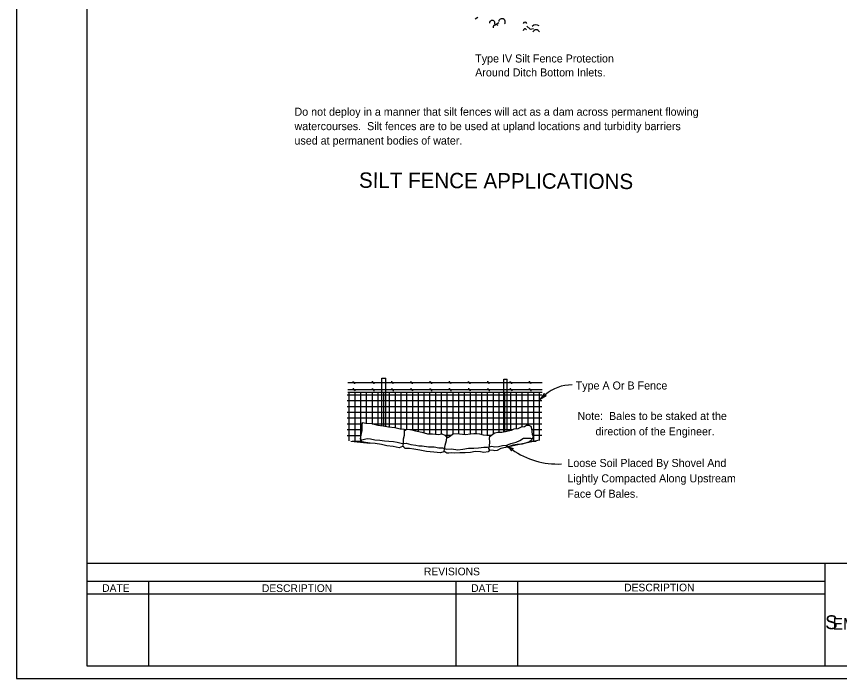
# Model space of a CAD drawing. Extents: x 539344 to 540004, y 1574686 to 1575110.
# Drawn here: x 539344 to 539600.9, y 1574686.5 to 1574893 of the extents above; entities that cross this region are included whole.
import ezdxf

# ---------------------------------------------------------------- set-up
doc = ezdxf.new("R2010")
doc.units = 0
for name, color, linetype in [('AdhocPoint_dp', 7, 'Continuous'), ('Default', 7, 'Continuous'), ('Logo_dp', 7, 'Continuous'), ('PlotBorder_dp', 7, 'Continuous'), ('ScratchEle_dp', 7, 'Continuous'), ('SheetBorder_dp', 7, 'Continuous'), ('SheetLines_dp', 7, 'Continuous'), ('TextMisc', 7, 'Continuous')]:
    doc.layers.add(name, color=color, linetype=linetype)

msp = doc.modelspace()

# ---------------------------------------------------------------- linework, layer by layer
at = {"layer": 'AdhocPoint_dp'}
msp.add_line((539343.95, 1574686.45), (539343.95, 1574686.45), dxfattribs=at)
at = {"layer": 'Default'}
for p, q in [((539487.11, 1574892.32), (539488.04, 1574892.79)), ((539493.16, 1574890.34), (539494.56, 1574891.16)), ((539503.28, 1574889.99), (539504.33, 1574889.06)), ((539504.33, 1574889.06), (539505.38, 1574889.29)), ((539458.05, 1574765.36), (539458.05, 1574780.14)), ((539458.05, 1574780.14), (539459.27, 1574780.14)), ((539459.27, 1574765.12), (539459.27, 1574780.14)), ((539496.14, 1574763.43), (539496.14, 1574779.9)), ((539496.14, 1574779.9), (539497.18, 1574779.9)), ((539497.18, 1574763.68), (539497.18, 1574779.9)), ((539447.41, 1574778.78), (539508.05, 1574778.78)), ((539447.45, 1574776.59), (539508.05, 1574776.59)), ((539447.2, 1574774.96), (539507.98, 1574774.96)), ((539447.45, 1574775.8), (539508.05, 1574775.8)), ((539447.76, 1574775.8), (539447.76, 1574760.62)), ((539449.56, 1574775.8), (539449.56, 1574760.41)), ((539451.36, 1574775.8), (539451.36, 1574760.21)), ((539453.16, 1574775.8), (539453.16, 1574766.09)), ((539454.96, 1574775.8), (539454.96, 1574765.96)), ((539456.76, 1574775.8), (539456.76, 1574765.53)), ((539458.56, 1574775.8), (539458.56, 1574765.28)), ((539460.35, 1574775.82), (539460.35, 1574764.91)), ((539462.15, 1574775.82), (539462.15, 1574764.73)), ((539463.95, 1574775.82), (539463.95, 1574764.38)), ((539465.75, 1574775.82), (539465.75, 1574764.29)), ((539467.55, 1574775.82), (539467.55, 1574763.96)), ((539469.35, 1574775.82), (539469.35, 1574763.56)), ((539471.15, 1574775.82), (539471.15, 1574763.16)), ((539472.95, 1574775.82), (539472.95, 1574762.84)), ((539474.75, 1574775.82), (539474.75, 1574762.74)), ((539476.55, 1574775.84), (539476.55, 1574762.8)), ((539478.35, 1574775.84), (539478.35, 1574761.54)), ((539480.15, 1574775.84), (539480.15, 1574762.67)), ((539481.95, 1574775.84), (539481.95, 1574762.8)), ((539483.75, 1574775.84), (539483.75, 1574762.61)), ((539485.55, 1574775.84), (539485.55, 1574762.74)), ((539487.35, 1574775.84), (539487.35, 1574762.88)), ((539489.15, 1574775.84), (539489.15, 1574762.61)), ((539490.95, 1574775.84), (539490.95, 1574762.36)), ((539492.75, 1574775.86), (539492.75, 1574762.81)), ((539494.55, 1574775.86), (539494.55, 1574763.28)), ((539496.35, 1574775.86), (539496.35, 1574763.45)), ((539498.15, 1574775.86), (539498.15, 1574763.9)), ((539499.95, 1574775.86), (539499.95, 1574764.42)), ((539501.75, 1574775.86), (539501.75, 1574765.01)), ((539503.55, 1574775.86), (539503.55, 1574765.53)), ((539505.35, 1574775.86), (539505.35, 1574760.38)), ((539507.15, 1574775.86), (539507.15, 1574760.77)), ((539509.01, 1574774.95), (539508.81, 1574775.34)), ((539509.36, 1574774.64), (539509.01, 1574774.95)), ((539447.2, 1574773.15), (539507.98, 1574773.16)), ((539447.2, 1574771.36), (539507.98, 1574771.36)), ((539447.2, 1574769.56), (539507.98, 1574769.56)), ((539447.2, 1574767.76), (539507.98, 1574767.76)), ((539447.2, 1574765.9), (539451.93, 1574765.9)), ((539447.2, 1574764.1), (539451.87, 1574764.1)), ((539454.98, 1574765.96), (539507.98, 1574765.96)), ((539464.99, 1574764.12), (539465.51, 1574764.12)), ((539466.8, 1574764.16), (539498.96, 1574764.16)), ((539504.8, 1574764.16), (539507.98, 1574764.16)), ((539447.2, 1574762.3), (539451.56, 1574762.3)), ((539477.72, 1574762.34), (539479.67, 1574762.34)), ((539491.7, 1574762.36), (539492.16, 1574762.36)), ((539505.09, 1574762.36), (539507.98, 1574762.36)), ((539448.31, 1574760.56), (539454.3, 1574759.87)), ((539448.8, 1574760.5), (539451.66, 1574760.5)), ((539507.26, 1574760.8), (539496.6, 1574758.49)), ((539504.4, 1574760.56), (539506.16, 1574760.56)), ((539504.45, 1574760.59), (539504.45, 1574760.19)), ((539498.55, 1574757.49), (539498.73, 1574757.92)), ((539498.73, 1574757.92), (539499.04, 1574758.24))]:
    msp.add_line(p, q, dxfattribs=at)
for points in [[(539507.21, 1574773.51), (539508.09, 1574774.37), (539508.42, 1574774.79), (539508.81, 1574775.34)], [(539507.21, 1574773.51), (539508.26, 1574774.16), (539508.74, 1574774.39), (539509.36, 1574774.64)], [(539507.98, 1574774.11), (539508.25, 1574774.29), (539508.43, 1574774.39), (539508.58, 1574774.48), (539508.71, 1574774.54), (539508.9, 1574774.62), (539508.76, 1574774.73), (539508.67, 1574774.9), (539508.59, 1574774.75), (539508.51, 1574774.65), (539508.42, 1574774.55), (539508.34, 1574774.45), (539508.25, 1574774.37), (539508.16, 1574774.27), (539507.98, 1574774.11)], [(539451.65, 1574760.52), (539451.35, 1574761.19), (539451.57, 1574762.35), (539451.88, 1574763.82), (539451.83, 1574765.25), (539451.99, 1574766.32), (539453.06, 1574766.1), (539454.86, 1574765.99), (539456.72, 1574765.54), (539458.42, 1574765.31), (539460.05, 1574764.94), (539462.13, 1574764.73), (539463.73, 1574764.4), (539464.99, 1574764.28), (539464.99, 1574762.25), (539464.7, 1574761.18), (539464.7, 1574759.66), (539464.47, 1574758.81), (539463.45, 1574758.46), (539461.61, 1574758.85), (539459.63, 1574759.04), (539457.96, 1574759.45), (539455.96, 1574759.76), (539454.34, 1574759.86), (539452.88, 1574760.05), (539451.9, 1574760.28), (539451.65, 1574760.52)], [(539464.99, 1574763.74), (539465.75, 1574764.29), (539467.01, 1574764.11), (539468.57, 1574763.7), (539470.5, 1574763.35), (539472.28, 1574762.82), (539473.8, 1574762.85), (539475.66, 1574762.62), (539476.76, 1574762.84), (539477.74, 1574762.35), (539478.23, 1574761.91), (539478.12, 1574760.58), (539477.74, 1574759.11), (539477.51, 1574758.1), (539477.34, 1574757.18), (539476.3, 1574756.83), (539474.26, 1574757.08), (539472, 1574757.3), (539469.93, 1574757.71), (539468.05, 1574757.97), (539466.63, 1574758.24), (539465.33, 1574758.19), (539464.87, 1574758.59), (539464.5, 1574758.92)], [(539491.64, 1574761.95), (539492.12, 1574762.33), (539492.73, 1574762.8), (539493.25, 1574763.1), (539494.19, 1574763.27), (539495.53, 1574763.3), (539496.58, 1574763.52), (539497.5, 1574763.77), (539498.54, 1574763.98), (539499.36, 1574764.33), (539500.59, 1574764.51), (539501.63, 1574765), (539502.61, 1574765.09), (539503.14, 1574765.55), (539503.94, 1574765.52), (539504.58, 1574765.2), (539504.79, 1574764.5), (539504.82, 1574763.39), (539504.99, 1574762.69), (539505.24, 1574761.85), (539504.77, 1574760.82), (539504.11, 1574760.35), (539503.18, 1574759.94), (539501.82, 1574759.62), (539500.32, 1574759.5), (539498.91, 1574759.31), (539497.79, 1574758.89), (539496.64, 1574758.5), (539495.22, 1574758.21), (539494.07, 1574757.64), (539493.33, 1574757.45), (539492.87, 1574757.65), (539491.67, 1574757.7)], [(539451.49, 1574760.89), (539452.15, 1574761.05), (539453.44, 1574761.3), (539454.53, 1574761.24), (539455.85, 1574760.95), (539457.35, 1574760.82), (539458.83, 1574760.59), (539460.21, 1574760.55), (539461.65, 1574760.36), (539462.85, 1574760.17), (539464.44, 1574759.83), (539465.57, 1574759.86), (539467.1, 1574759.47), (539468.62, 1574759.28), (539469.54, 1574759.04), (539470.62, 1574759.03), (539472.58, 1574758.78), (539474.34, 1574758.71), (539475.82, 1574758.47), (539476.94, 1574758.4), (539478.25, 1574758.01), (539479.79, 1574758.09), (539481.75, 1574757.85), (539483.29, 1574758.01), (539485.06, 1574758.29), (539486.76, 1574758.28), (539488.22, 1574758.45), (539489.86, 1574758.66), (539491, 1574758.68), (539492.31, 1574758.97), (539493.23, 1574758.72), (539494.45, 1574758.81), (539495.67, 1574759.11), (539497.01, 1574759.22), (539498.34, 1574759.79), (539499.94, 1574760.21), (539501.13, 1574760.74), (539502.24, 1574761.41), (539503.52, 1574761.47), (539504.5, 1574761.48), (539505.01, 1574761.34)], [(539478.19, 1574761.47), (539478.85, 1574761.75), (539479.56, 1574762.26), (539480.44, 1574762.87), (539482.26, 1574762.78), (539484.1, 1574762.57), (539485.74, 1574762.76), (539486.75, 1574762.9), (539487.63, 1574762.87), (539488.5, 1574762.81), (539489.64, 1574762.46), (539490.76, 1574762.38), (539491.7, 1574762.35), (539491.57, 1574761.48), (539491.6, 1574760.2), (539491.49, 1574759.05), (539491.34, 1574758.24), (539491.67, 1574757.7), (539491.17, 1574757.2), (539489.87, 1574756.99), (539488.81, 1574757.18), (539487.13, 1574757.25), (539485.66, 1574756.96), (539484, 1574756.89), (539482.41, 1574756.89), (539480.82, 1574756.74), (539479.86, 1574756.85), (539478.9, 1574756.72), (539478.3, 1574756.76), (539477.39, 1574757.42)], [(539496.79, 1574759.18), (539497.9, 1574758.62), (539498.4, 1574758.44), (539499.04, 1574758.24)], [(539496.79, 1574759.18), (539497.75, 1574758.39), (539498.12, 1574758), (539498.55, 1574757.49)], [(539497.61, 1574758.64), (539497.87, 1574758.44), (539498.02, 1574758.3), (539498.15, 1574758.18), (539498.24, 1574758.08), (539498.39, 1574757.93), (539498.45, 1574758.09), (539498.58, 1574758.23), (539498.41, 1574758.26), (539498.29, 1574758.3), (539498.17, 1574758.36), (539498.05, 1574758.4), (539497.94, 1574758.46), (539497.82, 1574758.52), (539497.61, 1574758.64)]]:
    msp.add_lwpolyline(points, dxfattribs=at)
for centre, radius, start, end in [((539495.51, 1574891.29), 1.03, 325.2278, 170.0212), ((539492.48, 1574890.97), 0.847, 341.695, 183.1066), ((539493.67, 1574889.55), 0.936, 40.2418, 183.3251), ((539502.74, 1574890.69), 0.564, 12.6804, 167.3196), ((539506.11, 1574888.61), 1.77, 54.4144, 131.3157), ((539502.69, 1574888.65), 0.522, 21.3706, 195.4993), ((539506.2, 1574887.74), 1.13, 22.894, 157.106), ((539449.38, 1574779.17), 0.388, 174.2815, 250.0227), ((539455.38, 1574779.17), 0.388, 174.2815, 250.0227), ((539461.38, 1574779.17), 0.388, 174.2815, 250.0227), ((539467.38, 1574779.17), 0.388, 174.2815, 250.0227), ((539473.38, 1574779.17), 0.388, 174.2815, 250.0227), ((539479.38, 1574779.17), 0.388, 174.2815, 250.0227), ((539485.38, 1574779.17), 0.388, 174.2815, 250.0227), ((539491.38, 1574779.17), 0.388, 174.2815, 250.0227), ((539498.38, 1574779.17), 0.388, 174.2815, 250.0227), ((539504.38, 1574779.17), 0.388, 174.2815, 250.0227), ((539449.42, 1574776.98), 0.388, 174.2815, 250.0227), ((539449.32, 1574778.79), 0.073, 0, 180), ((539449.32, 1574778.79), 0.073, 180, 0), ((539449.36, 1574776.59), 0.073, 0, 180), ((539449.36, 1574776.59), 0.073, 180, 0), ((539449.25, 1574778.4), 0.388, 354.2815, 69.465), ((539449.29, 1574776.2), 0.388, 354.2815, 69.465), ((539455.42, 1574776.98), 0.388, 174.2815, 250.0227), ((539455.32, 1574778.79), 0.073, 0, 180), ((539455.32, 1574778.79), 0.073, 180, 0), ((539455.36, 1574776.59), 0.073, 0, 180), ((539455.36, 1574776.59), 0.073, 180, 0), ((539455.25, 1574778.4), 0.388, 354.2815, 69.465), ((539455.29, 1574776.2), 0.388, 354.2815, 69.465), ((539461.42, 1574776.98), 0.388, 174.2815, 250.0227), ((539461.32, 1574778.79), 0.073, 0, 180), ((539461.32, 1574778.79), 0.073, 180, 0), ((539461.36, 1574776.59), 0.073, 0, 180), ((539461.36, 1574776.59), 0.073, 180, 0), ((539461.25, 1574778.4), 0.388, 354.2815, 69.465), ((539461.29, 1574776.2), 0.388, 354.2815, 69.465), ((539467.42, 1574776.98), 0.388, 174.2815, 250.0227), ((539467.32, 1574778.79), 0.073, 0, 180), ((539467.32, 1574778.79), 0.073, 180, 0), ((539467.36, 1574776.59), 0.073, 0, 180), ((539467.36, 1574776.59), 0.073, 180, 0), ((539467.25, 1574778.4), 0.388, 354.2815, 69.465), ((539467.29, 1574776.2), 0.388, 354.2815, 69.465), ((539473.42, 1574776.98), 0.388, 174.2815, 250.0227), ((539473.32, 1574778.79), 0.073, 0, 180), ((539473.32, 1574778.79), 0.073, 180, 0), ((539473.36, 1574776.59), 0.073, 0, 180), ((539473.36, 1574776.59), 0.073, 180, 0), ((539473.25, 1574778.4), 0.388, 354.2815, 69.465), ((539473.29, 1574776.2), 0.388, 354.2815, 69.465), ((539479.42, 1574776.98), 0.388, 174.2815, 250.0227), ((539479.32, 1574778.79), 0.073, 0, 180), ((539479.32, 1574778.79), 0.073, 180, 0), ((539479.36, 1574776.59), 0.073, 0, 180), ((539479.36, 1574776.59), 0.073, 180, 0), ((539479.25, 1574778.4), 0.388, 354.2815, 69.465), ((539479.29, 1574776.2), 0.388, 354.2815, 69.465), ((539485.42, 1574776.98), 0.388, 174.2815, 250.0227), ((539485.32, 1574778.79), 0.073, 0, 180), ((539485.32, 1574778.79), 0.073, 180, 0), ((539485.36, 1574776.59), 0.073, 0, 180), ((539485.36, 1574776.59), 0.073, 180, 0), ((539485.25, 1574778.4), 0.388, 354.2815, 69.465), ((539485.29, 1574776.2), 0.388, 354.2815, 69.465), ((539491.42, 1574776.98), 0.388, 174.2815, 250.0227), ((539491.32, 1574778.79), 0.073, 0, 180), ((539491.32, 1574778.79), 0.073, 180, 0), ((539491.36, 1574776.59), 0.073, 0, 180), ((539491.36, 1574776.59), 0.073, 180, 0), ((539491.25, 1574778.4), 0.388, 354.2815, 69.465), ((539491.29, 1574776.2), 0.388, 354.2815, 69.465), ((539498.42, 1574776.98), 0.388, 174.2815, 250.0227), ((539498.32, 1574778.79), 0.073, 0, 180), ((539498.32, 1574778.79), 0.073, 180, 0), ((539498.36, 1574776.59), 0.073, 0, 180), ((539498.36, 1574776.59), 0.073, 180, 0), ((539498.25, 1574778.4), 0.388, 354.2815, 69.465), ((539498.29, 1574776.2), 0.388, 354.2815, 69.465), ((539504.42, 1574776.98), 0.388, 174.2815, 250.0227), ((539504.32, 1574778.79), 0.073, 0, 180), ((539504.32, 1574778.79), 0.073, 180, 0), ((539504.36, 1574776.59), 0.073, 0, 180), ((539504.36, 1574776.59), 0.073, 180, 0), ((539504.25, 1574778.4), 0.388, 354.2815, 69.465), ((539504.29, 1574776.2), 0.388, 354.2815, 69.465), ((539517.37, 1574765.27), 12.79, 89.4818, 130.8193), ((539512.69, 1574777.12), 23.74, 233.9617, 273.3593)]:
    msp.add_arc(centre, radius, start, end, dxfattribs=at)
at = {"layer": 'PlotBorder_dp'}
msp.add_lwpolyline([(539343.95, 1574686.45), (540003.95, 1574686.45), (540003.95, 1575110.45), (539343.95, 1575110.45)], close=True, dxfattribs=at)
at = {"layer": 'SheetBorder_dp'}
for p, q in [((539365.95, 1575106.45), (539365.95, 1574690.45)), ((539365.95, 1574722.45), (539981.95, 1574722.45)), ((539365.95, 1574690.45), (539981.95, 1574690.45))]:
    msp.add_line(p, q, dxfattribs=at)
at = {"layer": 'SheetLines_dp'}
for p, q in [((539596.35, 1574722.45), (539596.35, 1574690.45)), ((539365.95, 1574716.85), (539596.35, 1574716.85)), ((539385.15, 1574716.85), (539385.15, 1574690.45)), ((539481.15, 1574716.85), (539481.15, 1574690.45)), ((539500.35, 1574716.85), (539500.35, 1574690.45)), ((539365.95, 1574712.85), (539596.35, 1574712.85))]:
    msp.add_line(p, q, dxfattribs=at)

# ---------------------------------------------------------------- texts
at = {"layer": 'Default'}
for s, p in [('Type IV Silt Fence Protection', (539487.17, 1574878.66)), ('Around Ditch Bottom Inlets.', (539487.17, 1574874.31)), ('Do not deploy in a manner that silt fences will act as a dam across permanent flowing', (539430.75, 1574862.05)), ('watercourses.  Silt fences are to be used at upland locations and turbidity barriers', (539430.75, 1574857.55)), ('used at permanent bodies of water.', (539430.75, 1574853.05)), ('Type A Or B Fence', (539518.54, 1574776.63))]:
    msp.add_text(s, height=2.5, dxfattribs=at).set_placement(p)
for s, height, rotation, p in [('SILT FENCE APPLICATIONS', 4.8, 359.7218, (539450.87, 1574839.57)), ('Note:  Bales to be staked at the', 2.5, 0, (539519.1, 1574767.12)), ('       direction of the Engineer.', 2.5, 0, (539518.21, 1574762.32)), ('Loose Soil Placed By Shovel And ', 2.5, 0, (539515.95, 1574752.46)), ('Lightly Compacted Along Upstream', 2.5, 0, (539515.95, 1574747.66)), ('Face Of Bales.', 2.5, 0, (539515.95, 1574742.86))]:
    msp.add_text(s, height=height, rotation=rotation, dxfattribs=at).set_placement(p)
at = {"layer": 'Logo_dp'}
for s, height, p in [('S', 4.32, (539596.45, 1574701.86)), ('EMINOLE       OUNTY', 3.6, (539598.79, 1574701.7))]:
    msp.add_text(s, height=height, dxfattribs=at).set_placement(p)
at = {"layer": 'ScratchEle_dp'}
for s, height, p in [('Angle:  90.0153', 0.1181, (539365.95, 1574722.39)), ('Sheet: 1', 0.118, (539365.95, 1574722.55)), ('Align: CH269', 0.1181, (539365.95, 1574722.24))]:
    msp.add_text(s, height=height, dxfattribs=at).set_placement(p)
at = {"layer": 'TextMisc'}
for s, rotation, p in [('REVISIONS', 360, (539471.17, 1574718.66)), ('DATE', 359.8693, (539370.71, 1574713.49)), ('DESCRIPTION', 0.0498, (539420.59, 1574713.44)), ('DATE', 359.8693, (539485.91, 1574713.47)), ('DESCRIPTION', 0.0498, (539533.69, 1574713.64))]:
    msp.add_text(s, height=2.4, rotation=rotation, dxfattribs=at).set_placement(p)

doc.saveas('drawing.dxf')
